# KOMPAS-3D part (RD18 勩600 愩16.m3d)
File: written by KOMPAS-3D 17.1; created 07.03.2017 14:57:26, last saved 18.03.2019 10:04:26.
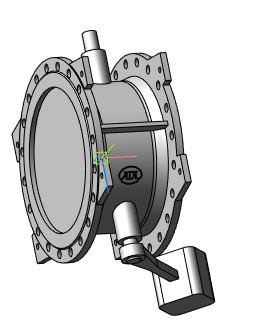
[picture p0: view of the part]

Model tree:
1. Операция без истории:2  (labels: Сталь 20  ГОСТ 1050-88)

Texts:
  RD18 Ду100 Ру16
  RD18 Ду150 Ру16
  RD18 Ду200 Ру16
  RD18 Ду250 Ру16
  RD18 Ду300 Ру16
  RD18 Ду350 Ру16
  RD18 Ду400 Ру10
  RD18 Ду400 Ру16
  RD18 Ду450 Ру10
  RD18 Ду450 Ру16
  RD18 Ду500 Ру10
  RD18 Ду500 Ру16
  RD18 Ду600 Ру10
  RD18 Ду600 Ру16
  RD18 Ду700 Ру10
  RD18 Ду700 Ру16
  RD18 Ду800 Ру10
  RD18 Ду800 Ру16
  RD18 Ду900 Ру10
  RD18 Ду900 Ру16
  RD18 Ду1000 Ру10
  RD18 Ду1000 Ру16
  RD18 Ду1200 Ру16
  RD18 Ду1400 Ру16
